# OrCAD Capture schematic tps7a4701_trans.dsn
size A; title: TPS7A4701 36V,1A, 4µVRMS, RF LDO Voltage Regulator; rev: 1.0; note: SBVS204F –JUNE 2012–REVISED SEPTEMBER 2014
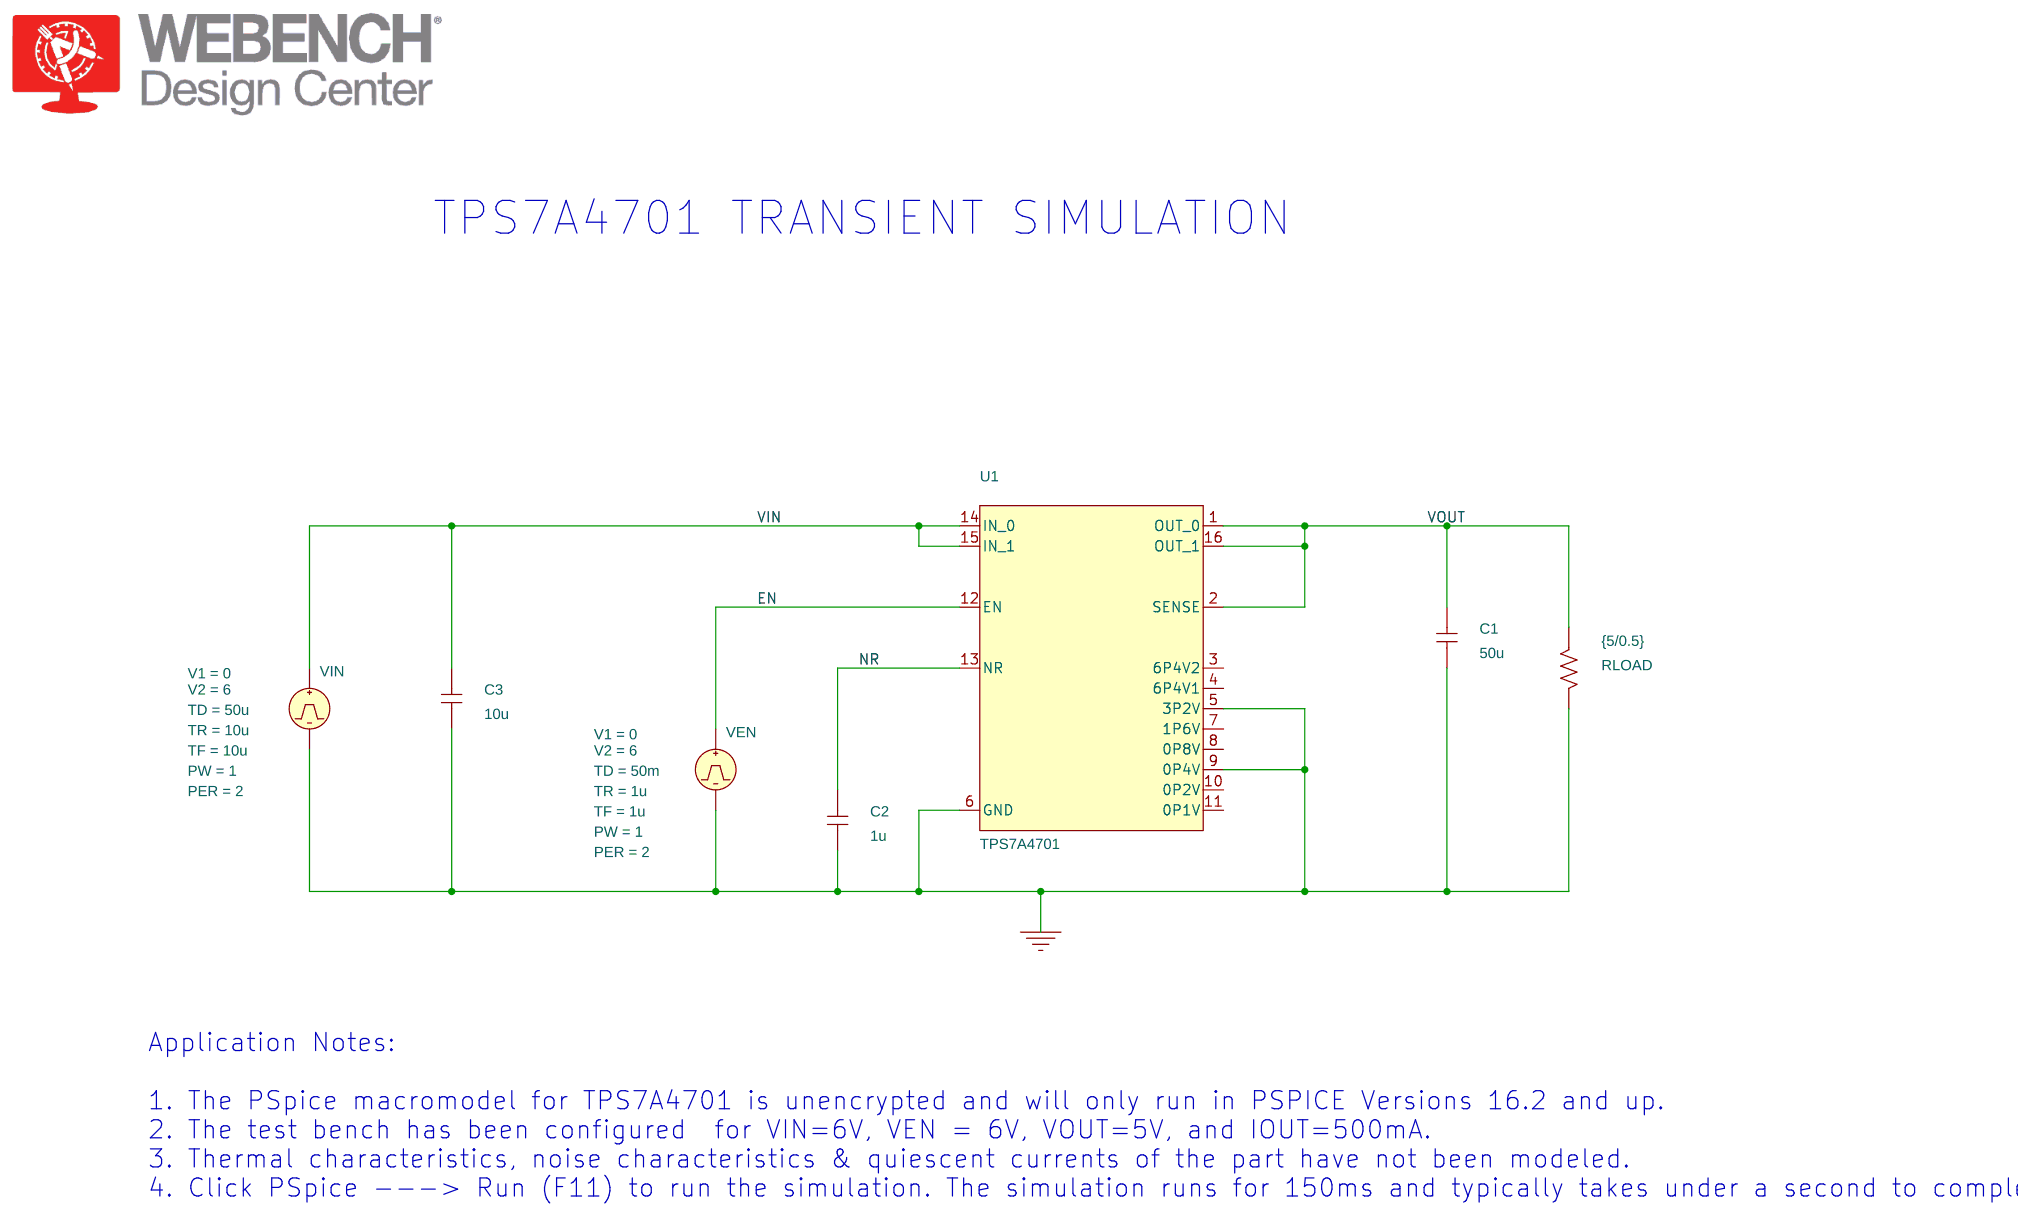
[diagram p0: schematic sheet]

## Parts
C1  50u  [RAD/CK05]
C2  1u  [RAD/CK05]
C3  10u  [RAD/CK05]
RLOAD  {5/0.5}  [AX/RC05]
U1  TPS7A4701
VEN  VPULSE
VIN  VPULSE

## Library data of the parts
C1-C3 = C
RLOAD = R
U1 = TPS7A4701
VEN = VPULSE: PER: 2; PW: 1; TD: 50m; TF: 1u; TR: 1u; V1: 0; V2: 6
VIN = VPULSE: PER: 2; PW: 1; TD: 50u; TF: 10u; TR: 10u; V1: 0; V2: 6

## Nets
VIN: C3.2 U1.14(IN_0) U1.15(IN_1) VIN.1(+)
0: C1.1 C2.1 C3.1 RLOAD.2 U1.5(3P2V) U1.6(GND) U1.9(0P4V) VEN.2(-) VIN.2(-)
EN: U1.12(EN) VEN.1(+)
NR: C2.2 U1.13(NR)
VOUT: C1.2 RLOAD.1 U1.1(OUT_0) U1.2(SENSE) U1.16(OUT_1)

Not connected (* = marked no-connect by the designer): U1 3(6P4V2) 4(6P4V1) 7(1P6V) 8(0P8V) 10(0P2V) 11(0P1V)

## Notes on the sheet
- TPS7A4701 TRANSIENT SIMULATION
- Application Notes:
  1. The PSpice macromodel for TPS7A4701 is unencrypted and will only run in PSPICE Versions 16.2 and up.
  2. The test bench has been configured  for VIN=6V, VEN = 6V, VOUT=5V, and IOUT=500mA.
  3. Thermal characteristics, noise characteristics & quiescent currents of the part have not been modeled.
  4. Click PSpice ---> Run (F11) to run the simulation. The simulation runs for 150ms and typically takes under a second to complete.
